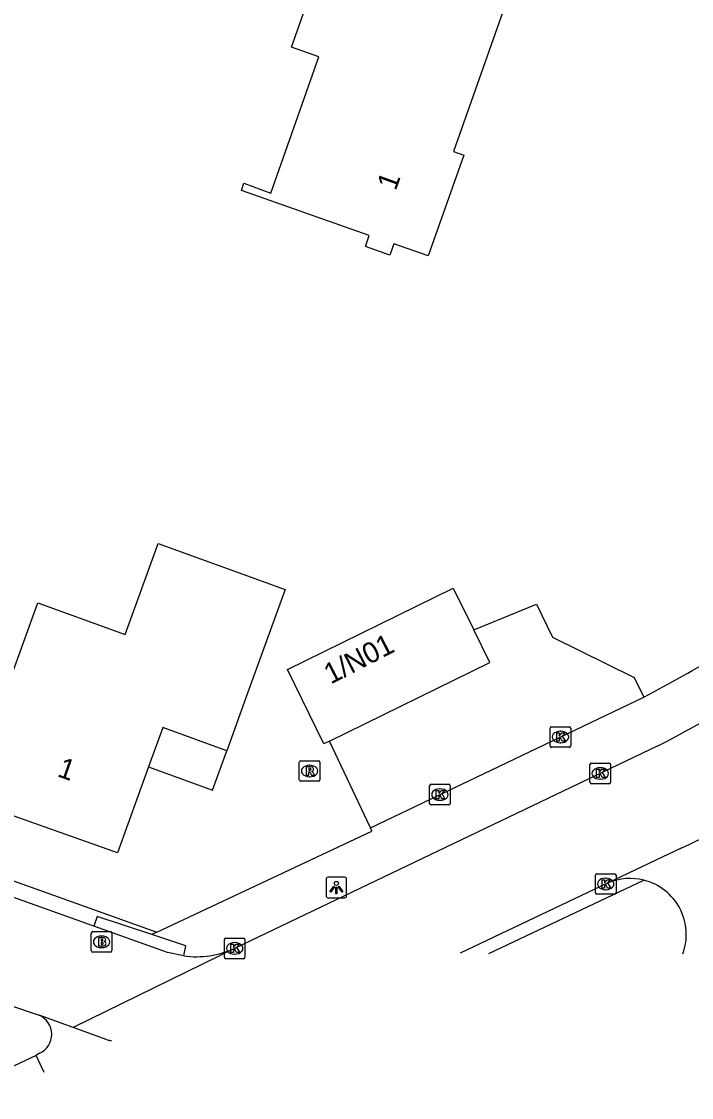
# Model space of a CAD drawing. Extents: x 163268 to 164360, y 381529 to 382285.
# Drawn here: x 163697.5 to 163730.1, y 381634.4 to 381686.6 of the extents above; entities that cross this region are included whole.
import ezdxf

# ---------------------------------------------------------------- set-up
doc = ezdxf.new("R2010")
doc.units = 0
for name, color, linetype in [('IMGEO_Brandkraan', 7, 'Continuous'), ('IMGEO_Fietspad_gesloten', 7, 'Continuous'), ('IMGEO_Fietspad_open', 7, 'Continuous'), ('IMGEO_Kolk', 7, 'Continuous'), ('IMGEO_Lichtpunt', 7, 'Continuous'), ('IMGEO_Pand', 7, 'Continuous'), ('IMGEO_Pand_nummerreeks', 7, 'Continuous'), ('IMGEO_Pand_overbouw', 7, 'Continuous'), ('IMGEO_Rijbaan_lokaal_open', 7, 'Continuous'), ('IMGEO_Rioolput', 7, 'Continuous'), ('IMGEO_Voetpad_open', 7, 'Continuous')]:
    doc.layers.add(name, color=color, linetype=linetype)

msp = doc.modelspace()

# ---------------------------------------------------------------- linework, layer by layer
at = {"layer": 'IMGEO_Brandkraan'}
for p, q in [((163700.93, 381641.487), (163700.93, 381642.339)), ((163701.005, 381642.413), (163701.857, 381642.413)), ((163701.418, 381642.193), (163701.443, 381642.193)), ((163701.931, 381642.339), (163701.931, 381641.487)), ((163701.857, 381641.413), (163701.005, 381641.413)), ((163701.441, 381641.633), (163701.416, 381641.633))]:
    msp.add_line(p, q, dxfattribs=at)
for points in [[(163700.93, 381641.487), (163700.93, 381642.339)], [(163701.005, 381642.413), (163701.857, 381642.413)], [(163701.931, 381642.339), (163701.931, 381641.487)], [(163701.278, 381642.113), (163701.278, 381641.713), (163701.491, 381641.713)], [(163701.509, 381642.113), (163701.278, 381642.113)], [(163701.457, 381642.032), (163701.403, 381642.032), (163701.403, 381641.956)], [(163701.403, 381641.956), (163701.456, 381641.956)], [(163701.465, 381641.88), (163701.403, 381641.88), (163701.403, 381641.799)], [(163701.403, 381641.799), (163701.465, 381641.799)], [(163701.857, 381641.413), (163701.005, 381641.413)]]:
    msp.add_lwpolyline(points, dxfattribs=at)
for centre, radius, start, end in [((163701.007, 381642.337), 0.0765, 91.552, 178.448), ((163701.007, 381642.337), 0.0765, 91.552, 178.448), ((163701.855, 381642.337), 0.0765, 1.552, 88.448), ((163701.855, 381642.337), 0.0765, 1.552, 88.448), ((163701.458, 381641.994), 0.0379, 267.8285, 90.9355), ((163701.466, 381641.839), 0.0404, 269.8759, 90.5077), ((163701.497, 381641.964), 0.251, 268.6676, 293.5347), ((163701.513, 381641.968), 0.145, 59.4692, 91.5367), ((163701.538, 381642.015), 0.0922, 285.5137, 58.1501), ((163701.543, 381641.823), 0.105, 301.3115, 78.989), ((163701.007, 381641.489), 0.0765, 181.552, 268.448), ((163701.007, 381641.489), 0.0765, 181.552, 268.448), ((163701.855, 381641.489), 0.0765, 271.552, 358.448), ((163701.855, 381641.489), 0.0765, 271.552, 358.448)]:
    msp.add_arc(centre, radius, start, end, dxfattribs=at)
for centre, major_axis, ratio, start_param, end_param in [((163701.417, 381641.913), (-0.387, 0.002), 0.722429, 4.712389, 7.853982), ((163701.442, 381641.913), (-0.39, 0.002), 0.717154, 1.570796, 4.712389)]:
    msp.add_ellipse(centre, major_axis=major_axis, ratio=ratio, start_param=start_param, end_param=end_param, dxfattribs=at)
at = {"layer": 'IMGEO_Fietspad_gesloten'}
for points in [[(163698.247, 381636.386), (163696.339, 381635.498), (163696.333, 381635.308), (163694.284, 381634.354)], [(163698.633, 381635.569), (163698.247, 381636.386)]]:
    msp.add_lwpolyline(points, dxfattribs=at)
at = {"layer": 'IMGEO_Fietspad_open'}
msp.add_lwpolyline([(163698.408, 381636.505), (163698.247, 381636.386)], dxfattribs=at)
for centre, radius, start, end in [((163727.113, 381642.176), 2.815, 76.0335, 112.1751), ((163727.138, 381642.28), 2.708, 339.6035, 76.0318), ((163698.015, 381637.422), 0.998, 293.1914, 67.8661)]:
    msp.add_arc(centre, radius, start, end, dxfattribs=at)
at = {"layer": 'IMGEO_Kolk'}
for p, q in [((163723.23, 381651.437), (163723.23, 381652.289)), ((163723.305, 381652.363), (163724.157, 381652.363)), ((163723.718, 381652.143), (163723.743, 381652.143)), ((163724.231, 381652.289), (163724.231, 381651.437)), ((163723.741, 381651.583), (163723.716, 381651.583)), ((163724.157, 381651.363), (163723.305, 381651.363)), ((163725.165, 381649.669), (163725.165, 381650.521)), ((163725.24, 381650.595), (163726.092, 381650.595)), ((163726.166, 381650.521), (163726.166, 381649.669)), ((163725.653, 381650.375), (163725.678, 381650.375)), ((163717.375, 381648.642), (163717.375, 381649.494)), ((163717.45, 381649.568), (163718.302, 381649.568)), ((163718.376, 381649.494), (163718.376, 381648.642)), ((163726.092, 381649.595), (163725.24, 381649.595)), ((163725.676, 381649.815), (163725.651, 381649.815)), ((163717.863, 381649.348), (163717.888, 381649.348)), ((163718.302, 381648.568), (163717.45, 381648.568)), ((163717.886, 381648.788), (163717.861, 381648.788)), ((163725.432, 381644.299), (163725.432, 381645.151)), ((163725.507, 381645.225), (163726.359, 381645.225)), ((163725.92, 381645.005), (163725.945, 381645.005)), ((163726.433, 381645.151), (163726.433, 381644.299)), ((163725.943, 381644.445), (163725.918, 381644.445)), ((163726.359, 381644.225), (163725.507, 381644.225)), ((163707.399, 381641.169), (163707.399, 381642.021)), ((163707.474, 381642.095), (163708.326, 381642.095)), ((163707.887, 381641.875), (163707.912, 381641.875)), ((163708.4, 381642.021), (163708.4, 381641.169)), ((163707.91, 381641.315), (163707.885, 381641.315)), ((163708.326, 381641.095), (163707.474, 381641.095))]:
    msp.add_line(p, q, dxfattribs=at)
for points in [[(163723.23, 381651.437), (163723.23, 381652.289)], [(163723.305, 381652.363), (163724.157, 381652.363)], [(163724.231, 381652.289), (163724.231, 381651.437)], [(163723.551, 381652.063), (163723.674, 381652.063), (163723.674, 381651.912), (163723.804, 381652.063), (163723.968, 381652.063), (163723.822, 381651.912), (163723.975, 381651.663), (163723.823, 381651.663), (163723.738, 381651.827), (163723.674, 381651.76), (163723.674, 381651.663), (163723.551, 381651.663), (163723.551, 381652.063)], [(163724.157, 381651.363), (163723.305, 381651.363)], [(163725.165, 381649.669), (163725.165, 381650.521)], [(163725.24, 381650.595), (163726.092, 381650.595)], [(163726.166, 381650.521), (163726.166, 381649.669)], [(163725.486, 381650.295), (163725.609, 381650.295), (163725.609, 381650.144), (163725.739, 381650.295), (163725.903, 381650.295), (163725.757, 381650.144), (163725.91, 381649.895), (163725.758, 381649.895), (163725.673, 381650.059), (163725.609, 381649.992), (163725.609, 381649.895), (163725.486, 381649.895), (163725.486, 381650.295)], [(163717.375, 381648.642), (163717.375, 381649.494)], [(163717.45, 381649.568), (163718.302, 381649.568)], [(163718.376, 381649.494), (163718.376, 381648.642)], [(163726.092, 381649.595), (163725.24, 381649.595)], [(163717.696, 381649.268), (163717.819, 381649.268), (163717.819, 381649.117), (163717.949, 381649.268), (163718.113, 381649.268), (163717.967, 381649.117), (163718.12, 381648.868), (163717.968, 381648.868), (163717.883, 381649.032), (163717.819, 381648.965), (163717.819, 381648.868), (163717.696, 381648.868), (163717.696, 381649.268)], [(163718.302, 381648.568), (163717.45, 381648.568)], [(163725.432, 381644.299), (163725.432, 381645.151)], [(163725.507, 381645.225), (163726.359, 381645.225)], [(163725.753, 381644.925), (163725.876, 381644.925), (163725.876, 381644.774), (163726.006, 381644.925), (163726.17, 381644.925), (163726.024, 381644.774), (163726.177, 381644.525), (163726.025, 381644.525), (163725.94, 381644.689), (163725.876, 381644.622), (163725.876, 381644.525), (163725.753, 381644.525), (163725.753, 381644.925)], [(163726.433, 381645.151), (163726.433, 381644.299)], [(163726.359, 381644.225), (163725.507, 381644.225)], [(163707.399, 381641.169), (163707.399, 381642.021)], [(163707.474, 381642.095), (163708.326, 381642.095)], [(163707.72, 381641.795), (163707.843, 381641.795), (163707.843, 381641.644), (163707.973, 381641.795), (163708.137, 381641.795), (163707.991, 381641.644), (163708.144, 381641.395), (163707.992, 381641.395), (163707.907, 381641.559), (163707.843, 381641.492), (163707.843, 381641.395), (163707.72, 381641.395), (163707.72, 381641.795)], [(163708.4, 381642.021), (163708.4, 381641.169)], [(163708.326, 381641.095), (163707.474, 381641.095)]]:
    msp.add_lwpolyline(points, dxfattribs=at)
for centre, start, end in [((163723.307, 381652.287), 91.552, 178.448), ((163723.307, 381652.287), 91.552, 178.448), ((163724.155, 381652.287), 1.552, 88.448), ((163724.155, 381652.287), 1.552, 88.448), ((163723.307, 381651.439), 181.552, 268.448), ((163723.307, 381651.439), 181.552, 268.448), ((163724.155, 381651.439), 271.552, 358.448), ((163724.155, 381651.439), 271.552, 358.448), ((163725.242, 381650.519), 91.552, 178.448), ((163725.242, 381650.519), 91.552, 178.448), ((163726.09, 381650.519), 1.552, 88.448), ((163726.09, 381650.519), 1.552, 88.448), ((163717.452, 381649.492), 91.552, 178.448), ((163717.452, 381649.492), 91.552, 178.448), ((163718.3, 381649.492), 1.552, 88.448), ((163718.3, 381649.492), 1.552, 88.448), ((163725.242, 381649.671), 181.552, 268.448), ((163725.242, 381649.671), 181.552, 268.448), ((163726.09, 381649.671), 271.552, 358.448), ((163726.09, 381649.671), 271.552, 358.448), ((163717.452, 381648.644), 181.552, 268.448), ((163717.452, 381648.644), 181.552, 268.448), ((163718.3, 381648.644), 271.552, 358.448), ((163718.3, 381648.644), 271.552, 358.448), ((163725.509, 381645.149), 91.552, 178.448), ((163725.509, 381645.149), 91.552, 178.448), ((163726.357, 381645.149), 1.552, 88.448), ((163726.357, 381645.149), 1.552, 88.448), ((163725.509, 381644.301), 181.552, 268.448), ((163725.509, 381644.301), 181.552, 268.448), ((163726.357, 381644.301), 271.552, 358.448), ((163726.357, 381644.301), 271.552, 358.448), ((163707.476, 381642.019), 91.552, 178.448), ((163707.476, 381642.019), 91.552, 178.448), ((163708.324, 381642.019), 1.552, 88.448), ((163708.324, 381642.019), 1.552, 88.448), ((163707.476, 381641.171), 181.552, 268.448), ((163707.476, 381641.171), 181.552, 268.448), ((163708.324, 381641.171), 271.552, 358.448), ((163708.324, 381641.171), 271.552, 358.448)]:
    msp.add_arc(centre, 0.0765, start, end, dxfattribs=at)
for centre, major_axis, ratio, start_param, end_param in [((163723.717, 381651.863), (-0.387, 0.002), 0.722429, 4.712389, 7.853982), ((163723.742, 381651.863), (-0.39, 0.002), 0.717154, 1.570796, 4.712389), ((163725.652, 381650.095), (-0.387, 0.002), 0.722429, 4.712389, 7.853982), ((163725.677, 381650.095), (-0.39, 0.002), 0.717154, 1.570796, 4.712389), ((163717.862, 381649.068), (-0.387, 0.002), 0.722429, 4.712389, 7.853982), ((163717.887, 381649.068), (-0.39, 0.002), 0.717154, 1.570796, 4.712389), ((163725.919, 381644.725), (-0.387, 0.002), 0.722429, 4.712389, 7.853982), ((163725.944, 381644.725), (-0.39, 0.002), 0.717154, 1.570796, 4.712389), ((163707.886, 381641.595), (-0.387, 0.002), 0.722429, 4.712389, 7.853982), ((163707.911, 381641.595), (-0.39, 0.002), 0.717154, 1.570796, 4.712389)]:
    msp.add_ellipse(centre, major_axis=major_axis, ratio=ratio, start_param=start_param, end_param=end_param, dxfattribs=at)
at = {"layer": 'IMGEO_Lichtpunt'}
for p, q in [((163712.344, 381644.956), (163712.344, 381644.149)), ((163712.344, 381644.956), (163712.344, 381644.149)), ((163713.246, 381645.051), (163712.438, 381645.051)), ((163713.246, 381645.051), (163712.438, 381645.051)), ((163713.34, 381644.149), (163713.34, 381644.956)), ((163713.34, 381644.149), (163713.34, 381644.956)), ((163712.438, 381644.055), (163713.246, 381644.055)), ((163712.438, 381644.055), (163713.246, 381644.055))]:
    msp.add_line(p, q, dxfattribs=at)
for points in [[(163712.718, 381644.62), (163712.757, 381644.592), (163712.569, 381644.33), (163712.531, 381644.357), (163712.718, 381644.62)], [(163712.82, 381644.572), (163712.867, 381644.572), (163712.867, 381644.25), (163712.82, 381644.25), (163712.82, 381644.572)], [(163712.93, 381644.592), (163712.968, 381644.619), (163713.155, 381644.357), (163713.116, 381644.329), (163712.93, 381644.592)]]:
    msp.add_lwpolyline(points, dxfattribs=at)
msp.add_circle((163712.843, 381644.754), 0.0994, dxfattribs=at)
for centre, start, end in [((163712.438, 381644.956), 90, 180), ((163712.438, 381644.956), 90, 180), ((163713.246, 381644.956), 0, 90), ((163713.246, 381644.956), 0, 90), ((163712.438, 381644.149), 180, 270), ((163712.438, 381644.149), 180, 270), ((163713.246, 381644.149), 270, 0), ((163713.246, 381644.149), 270, 360)]:
    msp.add_arc(centre, 0.0946, start, end, dxfattribs=at)
at = {"layer": 'IMGEO_Pand'}
for points in [[(163721.325, 381688.2), (163718.541, 381680.3), (163719.034, 381680.126), (163717.309, 381675.231), (163715.635, 381675.821), (163715.441, 381675.271), (163714.254, 381675.689), (163714.442, 381676.224), (163708.226, 381678.415), (163708.349, 381678.765), (163709.658, 381678.288), (163711.993, 381684.911), (163710.659, 381685.381), (163712.717, 381691.22)], [(163696.58, 381653.535), (163698.334, 381658.38), (163702.582, 381656.843), (163704.185, 381661.269), (163710.349, 381659.037), (163708.52, 381653.986), (163707.51, 381651.196), (163704.411, 381652.319), (163703.718, 381650.408), (163702.208, 381646.242), (163694.877, 381648.833), (163696.58, 381653.535)], [(163712.507, 381651.662), (163712.236, 381651.529), (163710.461, 381655.144), (163718.518, 381659.102), (163719.518, 381657.066)], [(163712.507, 381651.662), (163720.294, 381655.486), (163719.518, 381657.066)]]:
    msp.add_lwpolyline(points, dxfattribs=at)
at = {"layer": 'IMGEO_Pand_overbouw'}
msp.add_lwpolyline([(163707.51, 381651.196), (163704.411, 381652.319), (163703.718, 381650.408), (163706.818, 381649.284)], close=True, dxfattribs=at)
at = {"layer": 'IMGEO_Rijbaan_lokaal_open'}
for points in [[(163728.431, 381651.417), (163707.897, 381641.593)], [(163701.053, 381642.681), (163690.54, 381646.438)], [(163729.638, 381646.484), (163726.05, 381644.783)], [(163726.05, 381644.783), (163718.862, 381641.357)], [(163705.423, 381641.228), (163704.64, 381641.399), (163701.053, 381642.681)], [(163707.897, 381641.593), (163700.047, 381637.754)], [(163696.905, 381638.85), (163698.391, 381638.347)], [(163700.047, 381637.754), (163698.391, 381638.347)], [(163701.705, 381637.16), (163700.047, 381637.754)]]:
    msp.add_lwpolyline(points, dxfattribs=at)
for centre, radius, start, end in [((163679.991, 381744.224), 104.688, 297.5623, 306.4746), ((163698.206, 381714.612), 75.029, 294.76703, 299.52352), ((163706.014, 381645.787), 4.597, 262.61, 294.1751), ((163704.866, 381648.1), 11.387, 253.8852, 254.9999)]:
    msp.add_arc(centre, radius, start, end, dxfattribs=at)
at = {"layer": 'IMGEO_Rioolput'}
for p, q in [((163711.041, 381649.786), (163711.041, 381650.638)), ((163711.116, 381650.712), (163711.968, 381650.712)), ((163712.042, 381650.638), (163712.042, 381649.786)), ((163711.529, 381650.492), (163711.554, 381650.492)), ((163711.968, 381649.712), (163711.116, 381649.712)), ((163711.552, 381649.932), (163711.527, 381649.932))]:
    msp.add_line(p, q, dxfattribs=at)
for points in [[(163711.041, 381649.786), (163711.041, 381650.638)], [(163711.116, 381650.712), (163711.968, 381650.712)], [(163712.042, 381650.638), (163712.042, 381649.786)], [(163711.63, 381650.41), (163711.378, 381650.412), (163711.378, 381650.012)], [(163711.378, 381650.012), (163711.502, 381650.012), (163711.502, 381650.174), (163711.513, 381650.174)], [(163711.556, 381650.331), (163711.502, 381650.331), (163711.502, 381650.25)], [(163711.502, 381650.25), (163711.554, 381650.25)], [(163711.56, 381650.145), (163711.631, 381650.012), (163711.771, 381650.012), (163711.706, 381650.138)], [(163711.968, 381649.712), (163711.116, 381649.712)]]:
    msp.add_lwpolyline(points, dxfattribs=at)
for centre, radius, start, end in [((163711.118, 381650.636), 0.0765, 91.552, 178.448), ((163711.118, 381650.636), 0.0765, 91.552, 178.448), ((163711.966, 381650.636), 0.0765, 1.552, 88.448), ((163711.966, 381650.636), 0.0765, 1.552, 88.448), ((163711.512, 381650.121), 0.0533, 26.0293, 88.6989), ((163711.538, 381650.439), 0.19, 274.7715, 282.9687), ((163711.562, 381650.235), 0.0964, 77.0061, 93.1865), ((163711.576, 381650.292), 0.0378, 276.6634, 79.6772), ((163711.629, 381650.3), 0.109, 350.3612, 89.416), ((163711.627, 381650.3), 0.112, 277.5842, 350.9817), ((163711.611, 381650.085), 0.108, 29.5134, 73.7905), ((163711.118, 381649.788), 0.0765, 181.552, 268.448), ((163711.118, 381649.788), 0.0765, 181.552, 268.448), ((163711.966, 381649.788), 0.0765, 271.552, 358.448), ((163711.966, 381649.788), 0.0765, 271.552, 358.448)]:
    msp.add_arc(centre, radius, start, end, dxfattribs=at)
for centre, major_axis, ratio, start_param, end_param in [((163711.528, 381650.212), (-0.387, 0.002), 0.722429, 4.712389, 7.853982), ((163711.553, 381650.212), (-0.39, 0.002), 0.717154, 1.570796, 4.712389)]:
    msp.add_ellipse(centre, major_axis=major_axis, ratio=ratio, start_param=start_param, end_param=end_param, dxfattribs=at)
at = {"layer": 'IMGEO_Voetpad_open'}
for points in [[(163629.716, 381668.998), (163704.116, 381642.385)], [(163719.518, 381657.066), (163722.573, 381658.314), (163723.351, 381656.715), (163727.31, 381654.748), (163727.79, 381653.802)], [(163714.503, 381647.459), (163727.79, 381653.802)], [(163714.503, 381647.459), (163712.507, 381651.662)], [(163704.116, 381642.385), (163714.571, 381647.298), (163714.503, 381647.459)], [(163720.249, 381641.354), (163727.792, 381644.908)], [(163703.879, 381642.266), (163701.221, 381643.151), (163701.053, 381642.681)], [(163704.116, 381642.385), (163703.879, 381642.266)], [(163705.423, 381641.228), (163705.529, 381641.716), (163703.879, 381642.266)]]:
    msp.add_lwpolyline(points, dxfattribs=at)
msp.add_arc((163678.641, 381746.031), 104.508, 298.05329, 302.79447, dxfattribs=at)

# ---------------------------------------------------------------- texts
at = {"layer": 'IMGEO_Pand_nummerreeks'}
for s, rotation, p in [('1', 70.0787, (163715.725, 381678.366)), ('1/N01', 27.165, (163712.567, 381654.41)), ('1', 340.5366, (163699.23, 381649.968))]:
    msp.add_text(s, height=1, rotation=rotation, dxfattribs=at).set_placement(p)

doc.saveas('drawing.dxf')
